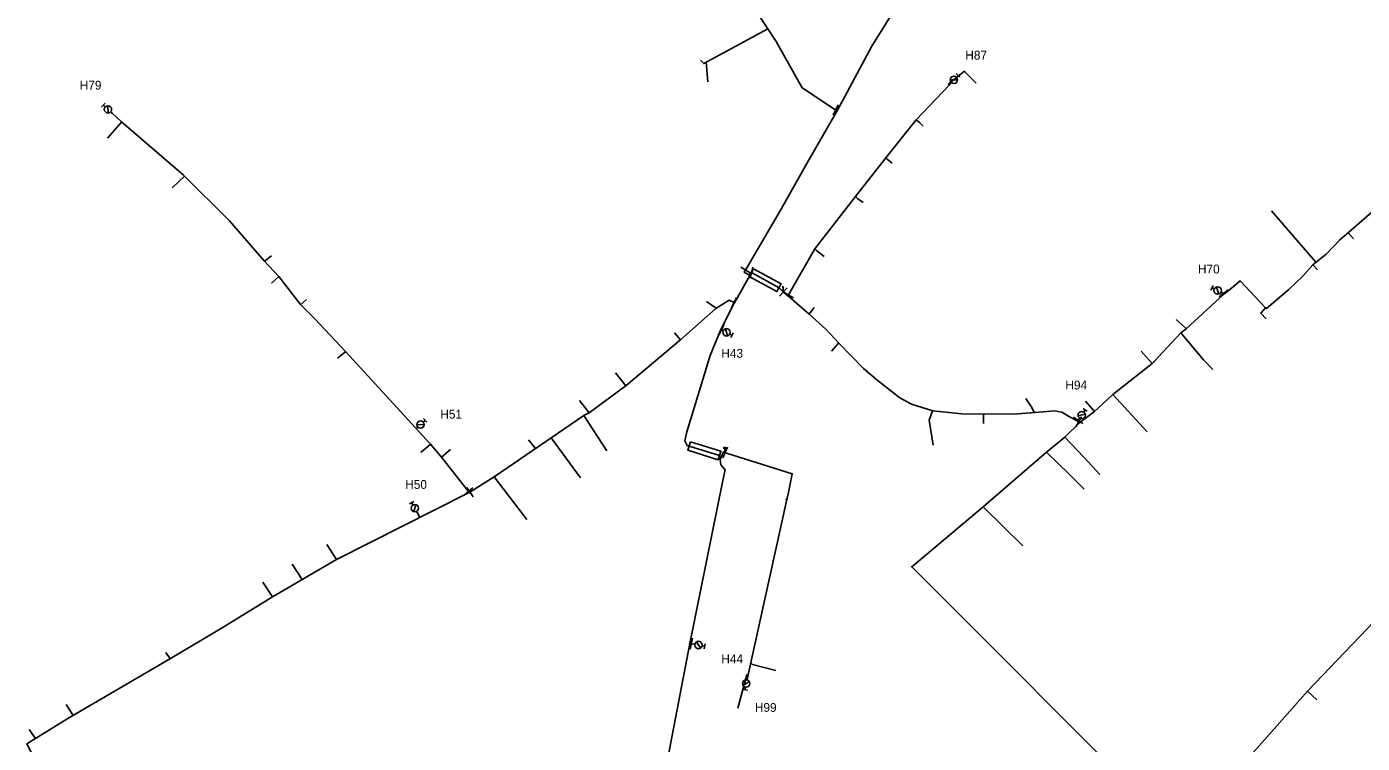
# Model space of a CAD drawing. Extents: x -548873 to -538270, y -1201997 to -1192514.
# Drawn here: x -547608.6 to -547306.8, y -1195915.9 to -1195753.9 of the extents above; entities that cross this region are included whole.
import ezdxf

# ---------------------------------------------------------------- set-up
doc = ezdxf.new("R2010")
doc.units = 0
for name, color, linetype in [('KN_HRAN_STÁTNÍ', 7, 'Continuous'), ('KN_PARC_Č', 7, 'Continuous'), ('KN_VKP_HRAN_SPORNÁ', 7, 'Continuous'), ('PK_PARC_Čv', 7, 'Continuous'), ('Vrstva 29', 7, 'Continuous'), ('Vrstva 37', 7, 'Continuous'), ('Vrstva 39', 7, 'Continuous')]:
    doc.layers.add(name, color=color, linetype=linetype)

# ---------------------------------------------------------------- blocks, each defined once
blk = doc.blocks.new('160')
at = {"layer": 'KN_HRAN_STÁTNÍ'}
blk.add_circle((0, 0), 0.0458, dxfattribs=at)
blk = doc.blocks.new('147')
at = {"layer": 'KN_HRAN_STÁTNÍ'}
blk.add_line((0, 1.27), (0, -1.27), dxfattribs=at)
blk = doc.blocks.new('133')
at = {"layer": 'KN_HRAN_STÁTNÍ'}
for p, q in [((0.28, 0), (0, 0)), ((0.54, 0.58), (1.7, -0.58)), ((1.94, 0), (2.52, 0)), ((2.52, 0.58), (2.52, -0.58))]:
    blk.add_line(p, q, dxfattribs=at)
blk.add_circle((1.11, 0), 0.825, dxfattribs=at)
blk = doc.blocks.new('150')
at = {"layer": 'KN_HRAN_STÁTNÍ'}
blk.add_line((0, 1.27), (0, -1.27), dxfattribs=at)
blk = doc.blocks.new('124')
at = {"layer": 'KN_HRAN_STÁTNÍ'}
for q in [(-0.19, 1.22), (-0.19, 0.92), (0.19, 1.22), (0, 0), (0.19, 0.92)]:
    blk.add_line((0, 1.07), q, dxfattribs=at)
blk = doc.blocks.new('128')
at = {"layer": 'KN_HRAN_STÁTNÍ'}
for p, q in [((-0.19, 1.06), (-0.43, 1.15)), ((-0.36, 0.84), (-0.19, 1.06)), ((-0.19, 1.06), (-0.02, 1.25)), ((-0.19, 1.06), (0, 0)), ((0.05, 0.95), (-0.19, 1.06)), ((-0.1, 1), (0.41, 0.91)), ((-0.07, 0.82), (0.17, 0.96)), ((0.17, 0.96), (-0.02, 1.13)), ((0.17, 0.96), (0, 0)), ((0.19, 1.21), (0.17, 0.96)), ((0.17, 0.96), (0.38, 1.08)), ((0.36, 0.77), (0.17, 0.96))]:
    blk.add_line(p, q, dxfattribs=at)

msp = doc.modelspace()

# ---------------------------------------------------------------- linework, layer by layer
at = {"layer": 'KN_PARC_Č'}
for points in [[(-547441.111, -1195754.422), (-547455.603, -1195762.254), (-547456.318, -1195761.516)], [(-547455.085, -1195761.974), (-547454.684, -1195766.387)], [(-547400.179, -1195767.138), (-547400.328, -1195766.986), (-547399.963, -1195766.62), (-547396.696, -1195763.997), (-547396.579, -1195764.113), (-547396.341, -1195764.352), (-547394.023, -1195766.72)], [(-547407.612, -1195774.975), (-547406.822, -1195775.59), (-547406.001, -1195776.388)], [(-547587.165, -1195775.494), (-547590.347, -1195779.106)], [(-547414.479, -1195783.569), (-547414.147, -1195783.843), (-547413.002, -1195784.775)], [(-547572.927, -1195787.722), (-547575.705, -1195790.36)], [(-547421.344, -1195792.329), (-547420.755, -1195792.797), (-547419.612, -1195793.623)], [(-547317.254, -1195807.158), (-547327.304, -1195795.558)], [(-547309.968, -1195800.545), (-547308.77, -1195801.88)], [(-547430.516, -1195804.133), (-547430.099, -1195804.49), (-547428.425, -1195805.875)], [(-547554.859, -1195806.921), (-547553.305, -1195805.714)], [(-547317.968, -1195807.731), (-547316.922, -1195808.892)], [(-547551.66, -1195810.37), (-547553.281, -1195811.855)], [(-547546.721, -1195816.752), (-547545.362, -1195815.605)], [(-547452.782, -1195817.538), (-547454.961, -1195815.998)], [(-547431.781, -1195818.928), (-547430.687, -1195817.356)], [(-547328.626, -1195817.484), (-547329.726, -1195818.651), (-547328.494, -1195819.929)], [(-547346.549, -1195822.171), (-547348.812, -1195820.119)], [(-547460.852, -1195824.659), (-547462.178, -1195823.122)], [(-547347.764, -1195823.113), (-547342.677, -1195829.179), (-547340.526, -1195831.387)], [(-547425.109, -1195825.409), (-547426.771, -1195827.282)], [(-547536.542, -1195827.389), (-547538.359, -1195828.808)], [(-547354.284, -1195830.016), (-547356.767, -1195827.264)], [(-547473.19, -1195835.059), (-547475.523, -1195832.124)], [(-547481.53, -1195841.2), (-547483.651, -1195838.429)], [(-547380.949, -1195841.122), (-547381.009, -1195840.953), (-547381.473, -1195840.007), (-547382.792, -1195837.99)], [(-547367.307, -1195840.86), (-547369.366, -1195838.544)], [(-547363.145, -1195837.018), (-547355.407, -1195845.49)], [(-547482.687, -1195841.8), (-547477.492, -1195849.807)], [(-547403.881, -1195840.742), (-547404.672, -1195842.813), (-547403.775, -1195848.488)], [(-547392.362, -1195841.445), (-547392.372, -1195843.638)], [(-547493.63, -1195849.273), (-547495.195, -1195847.26)], [(-547490.083, -1195846.85), (-547483.472, -1195855.874)], [(-547373.978, -1195846.717), (-547369.772, -1195851.099), (-547369.542, -1195851.338), (-547366.115, -1195855.158)], [(-547517.358, -1195848.267), (-547519.538, -1195850.131)], [(-547514.874, -1195851.191), (-547512.867, -1195849.443)], [(-547378.124, -1195850.092), (-547373.004, -1195855.024), (-547369.626, -1195858.438)], [(-547502.943, -1195855.635), (-547495.559, -1195865.334)], [(-547436.772, -1195860.566), (-547437.03, -1195860.96)], [(-547392.437, -1195862.445), (-547383.478, -1195871.243)], [(-547538.585, -1195874.329), (-547540.805, -1195870.97)], [(-547439.861, -1195874.545), (-547440.034, -1195874.522)], [(-547546.319, -1195878.829), (-547548.597, -1195875.398)], [(-547553.079, -1195882.763), (-547555.214, -1195879.49)], [(-547576.222, -1195896.778), (-547577.201, -1195895.374)], [(-547444.975, -1195897.681), (-547444.601, -1195898.032), (-547439.279, -1195899.44)], [(-547445.578, -1195900.408), (-547445.773, -1195900.364), (-547445.871, -1195900.43), (-547447.912, -1195907.9)], [(-547319.192, -1195904.074), (-547317.077, -1195906.061)], [(-547598.125, -1195909.581), (-547599.654, -1195907.084)], [(-547606.64, -1195914.798), (-547608.058, -1195912.752)]]:
    msp.add_lwpolyline(points, dxfattribs=at)
at = {"layer": 'KN_VKP_HRAN_SPORNÁ'}
for points in [[(-547425.785, -1195772.759), (-547433.342, -1195767.71), (-547439.235, -1195757.255), (-547443.312, -1195751.099), (-547444.279, -1195749.64), (-547450.389, -1195739.691), (-547459.879, -1195725.68), (-547466.059, -1195717.114), (-547468.493, -1195713.113), (-547468.55, -1195710.024), (-547467.599, -1195689.001), (-547474.02, -1195665.116), (-547488.253, -1195647.01), (-547500.937, -1195632.883), (-547516.701, -1195620.349), (-547516.745, -1195620.314)], [(-547353.907, -1195674.777), (-547358.947, -1195681.231), (-547359.171, -1195687.793), (-547360.282, -1195690.048), (-547367.646, -1195697.265), (-547376.495, -1195705.645), (-547382.898, -1195712.235), (-547393.089, -1195723.345), (-547400.573, -1195732.935), (-547405.899, -1195740.503), (-547411.174, -1195747.949), (-547417.586, -1195758.304), (-547425.386, -1195772.82)], [(-547269.561, -1195765.274), (-547270.596, -1195766.141), (-547287.035, -1195779.881), (-547294.101, -1195786.683), (-547303.328, -1195794.687), (-547309.862, -1195800.458), (-547311.869, -1195802.1)], [(-547436.455, -1195814.564), (-547430.516, -1195804.134), (-547421.344, -1195792.329), (-547414.479, -1195783.569), (-547407.612, -1195774.975), (-547400.103, -1195767.058), (-547399.965, -1195766.913)], [(-547508.788, -1195858.964), (-547514.836, -1195851.236), (-547517.426, -1195848.187), (-547536.588, -1195827.339), (-547543.476, -1195819.949), (-547546.728, -1195816.745), (-547551.623, -1195810.41), (-547554.93, -1195806.844), (-547562.75, -1195797.813), (-547573.276, -1195787.375), (-547587.201, -1195775.463), (-547589.327, -1195773.469), (-547589.353, -1195773.445)], [(-547425.386, -1195772.82), (-547432.316, -1195784.838), (-547438.304, -1195795.553), (-547445.856, -1195808.424), (-547446.172, -1195808.918)], [(-547425.386, -1195772.82), (-547425.785, -1195772.759)], [(-547311.869, -1195802.1), (-547314.943, -1195805.308), (-547317.966, -1195807.729), (-547320.242, -1195810.343), (-547323.407, -1195813.352), (-547328.467, -1195817.647), (-547328.626, -1195817.484), (-547328.629, -1195817.481), (-547334.406, -1195811.367), (-547336.339, -1195812.999), (-547337.597, -1195814.087), (-547338.088, -1195814.408)], [(-547445.172, -1195810.15), (-547448.661, -1195816.302)], [(-547446.172, -1195808.918), (-547446.463, -1195809.412), (-547445.172, -1195810.15)], [(-547445.172, -1195810.15), (-547445.16, -1195809.509), (-547444.847, -1195809.496)], [(-547444.847, -1195809.496), (-547438.592, -1195812.909), (-547437.683, -1195813.835)], [(-547437.611, -1195813.905), (-547437.683, -1195813.835)], [(-547436.579, -1195814.781), (-547437.611, -1195813.905)], [(-547436.579, -1195814.781), (-547436.455, -1195814.564)], [(-547353.892, -1195829.692), (-547347.761, -1195823.111), (-547346.551, -1195822.173), (-547338.088, -1195814.408)], [(-547448.762, -1195816.252), (-547449.848, -1195815.721), (-547452.894, -1195817.607), (-547460.799, -1195824.614), (-547473.138, -1195835.021), (-547481.507, -1195841.188), (-547482.698, -1195841.806), (-547502.943, -1195855.635), (-547508.437, -1195859.105)], [(-547448.661, -1195816.302), (-547448.78, -1195816.543), (-547451.731, -1195822.33), (-547454.152, -1195828.2), (-547459.448, -1195845.518), (-547459.65, -1195846.468), (-547459.862, -1195847.55), (-547459.355, -1195848.577), (-547458.871, -1195848.709), (-547452.034, -1195850.825), (-547451.674, -1195851.182)], [(-547448.661, -1195816.302), (-547448.762, -1195816.252)], [(-547370.858, -1195843.241), (-547373.156, -1195841.974), (-547374.685, -1195841.045), (-547376.328, -1195840.772), (-547378.897, -1195840.944), (-547385.602, -1195841.526), (-547397.292, -1195841.387), (-547403.858, -1195840.749), (-547408.669, -1195839.269), (-547411.319, -1195837.786), (-547416.515, -1195833.753), (-547419.503, -1195831.152), (-547425.059, -1195825.461), (-547428.05, -1195822.298), (-547431.781, -1195818.928), (-547436.393, -1195814.926), (-547436.579, -1195814.781)], [(-547370.601, -1195843.396), (-547367.308, -1195840.86), (-547363.144, -1195837.018), (-547354.287, -1195830.019), (-547353.892, -1195829.692)], [(-547408.612, -1195875.991), (-547392.43, -1195862.44), (-547378.116, -1195850.085), (-547373.973, -1195846.713), (-547370.601, -1195843.396)], [(-547370.601, -1195843.396), (-547370.858, -1195843.241)], [(-547450.749, -1195850.155), (-547451.173, -1195850.009), (-547451.448, -1195850.61), (-547451.674, -1195851.182)], [(-547445.726, -1195901.074), (-547445.499, -1195900.051), (-547436.815, -1195860.769), (-547436.48, -1195859.171), (-547435.598, -1195854.968), (-547450.433, -1195850.288), (-547450.749, -1195850.155)], [(-547451.674, -1195851.182), (-547451.924, -1195851.77), (-547451.742, -1195852.962), (-547450.728, -1195854.049), (-547451.305, -1195856.509), (-547458.717, -1195893.288), (-547462.732, -1195914.137), (-547465.207, -1195927.077)], [(-547508.598, -1195859.206), (-547538.573, -1195874.322), (-547553.093, -1195882.771), (-547564.445, -1195889.747), (-547576.129, -1195896.724), (-547599.306, -1195910.271), (-547608.605, -1195916.011), (-547605.041, -1195922.864)], [(-547508.598, -1195859.206), (-547508.788, -1195858.964)], [(-547508.437, -1195859.105), (-547508.598, -1195859.206)], [(-547424.144, -1196016.765), (-547424.508, -1196016.405), (-547430.282, -1196010.688), (-547417.621, -1195996.885), (-547408.207, -1195986.765), (-547402.107, -1195980.091), (-547388.859, -1195965.775), (-547372.176, -1195948.007), (-547363.002, -1195938.001), (-547356.605, -1195931.025), (-547356.251, -1195929.577), (-547356.667, -1195928.147), (-547358.105, -1195926.546), (-547360.459, -1195924.19), (-547400.597, -1195884.014), (-547408.612, -1195875.991)], [(-547423.899, -1196017.008), (-547412.145, -1196004.69), (-547395.753, -1195987.042), (-547390.663, -1195981.436), (-547374.686, -1195963.838), (-547358.776, -1195946.603), (-547347.545, -1195935.094), (-547330.623, -1195917.023), (-547319.187, -1195904.069), (-547302.312, -1195886.45), (-547300.97, -1195886.17), (-547298.561, -1195886.625), (-547294.438, -1195888.916), (-547286.694, -1195896.655), (-547278.196, -1195905.147)]]:
    msp.add_lwpolyline(points, dxfattribs=at)
at = {"layer": 'PK_PARC_Čv'}
for points in [[(-547399.965, -1195766.913), (-547399.827, -1195766.767)], [(-547589.353, -1195773.445), (-547589.429, -1195773.373)], [(-547338.088, -1195814.408), (-547338.126, -1195814.19), (-547338.432, -1195814.053)], [(-547451.735, -1195822.34), (-547451.461, -1195822.475)], [(-547520.575, -1195844.761), (-547520.411, -1195844.61)], [(-547371.135, -1195843.088), (-547370.814, -1195842.617)], [(-547519.75, -1195864.83), (-547520.374, -1195863.699)], [(-547458.725, -1195893.327), (-547457.902, -1195893.444)], [(-547445.726, -1195901.074), (-547445.769, -1195901.27)]]:
    msp.add_lwpolyline(points, dxfattribs=at)
at = {"layer": 'Vrstva 37'}
for points in [[(-547444.368, -1195808.618), (-547438.113, -1195812.031), (-547439.071, -1195813.787), (-547445.326, -1195810.374), (-547444.368, -1195808.618)], [(-547458.575, -1195847.754), (-547451.738, -1195849.87), (-547452.33, -1195851.78), (-547459.167, -1195849.664), (-547458.575, -1195847.754)]]:
    msp.add_lwpolyline(points, dxfattribs=at)

# ---------------------------------------------------------------- block references
at = {"layer": 'PK_PARC_Čv'}
for name, p, xscale, yscale, rotation in [('133', (-547399.827, -1195766.767), 1.00000000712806, 1.00000000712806, 46.99999943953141), ('133', (-547589.429, -1195773.373), 1.00000000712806, 1.00000000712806, 136.99999943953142), ('133', (-547338.432, -1195814.053), 1.0225848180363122, 1.0225848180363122, 154.18102564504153), ('150', (-547338.126, -1195814.19), 1.000000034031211, 1.0000000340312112, -51.999999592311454), ('150', (-547451.598, -1195822.408), 1.0138865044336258, 1.0138865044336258, -27.56531359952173), ('133', (-547451.461, -1195822.475), 1.0138865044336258, 1.0138865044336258, -27.56531359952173), ('133', (-547370.814, -1195842.617), 0.9999999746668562, 0.999999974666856, 55.999999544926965), ('133', (-547520.411, -1195844.61), 1.00000000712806, 1.00000000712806, 43.0000005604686), ('150', (-547370.987, -1195842.871), 0.9999999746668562, 0.999999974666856, -124.00000045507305), ('133', (-547520.374, -1195863.699), 1.0000000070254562, 1.0000000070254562, 118.99999892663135), ('150', (-547458.428, -1195893.369), 1.0092050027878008, 1.0092050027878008, -11.116918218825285), ('133', (-547457.902, -1195893.444), 1.0092050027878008, 1.0092050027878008, -11.116918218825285), ('133', (-547445.769, -1195901.27), 1.0000000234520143, 1.0000000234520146, -101.99999938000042)]:
    msp.add_blockref(name, p, dxfattribs=dict(at, xscale=xscale, yscale=yscale, rotation=rotation))
at = {"layer": 'Vrstva 29'}
for name, p, xscale, yscale, rotation in [('160', (-547399.965, -1195766.913), 1.00000000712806, 1.00000000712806, 46.99999943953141), ('147', (-547425.785, -1195772.759), 1.0296949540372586, 1.0296949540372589, 155.86620948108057), ('160', (-547589.353, -1195773.445), 1.00000000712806, 1.00000000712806, -43.0000005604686), ('160', (-547425.386, -1195772.82), 1.0106518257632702, 1.0106518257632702, -151.83788426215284), ('160', (-547311.869, -1195802.1), 1.00000000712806, 1.00000000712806, 43.0000005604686), ('147', (-547446.172, -1195808.918), 1.0000000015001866, 1.0000000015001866, -120.99999982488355), ('147', (-547444.847, -1195809.496), 1.0028916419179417, 1.0028916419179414, 166.30279126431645), ('160', (-547445.172, -1195810.15), 0.999999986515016, 0.9999999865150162, -105.00000012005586), ('147', (-547437.611, -1195813.905), 1.0000000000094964, 1.0000000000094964, -42.000001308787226), ('160', (-547437.683, -1195813.835), 1.0000000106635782, 1.0000000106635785, 135.99999834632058), ('147', (-547436.455, -1195814.564), 1.0000000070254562, 1.0000000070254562, 61.000001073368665), ('160', (-547338.088, -1195814.408), 1.000000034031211, 1.0000000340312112, 38.000000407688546), ('147', (-547448.762, -1195816.252), 1.0138865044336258, 1.0138865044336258, 152.43468640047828), ('160', (-547448.661, -1195816.302), 0.9999999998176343, 0.9999999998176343, -116.9999993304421), ('160', (-547436.579, -1195814.781), 1.0000000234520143, 1.0000000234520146, -78.0000006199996), ('160', (-547353.892, -1195829.692), 1.0000000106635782, 1.0000000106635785, 44.00000165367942), ('147', (-547370.858, -1195843.241), 1.0037042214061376, 1.0037042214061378, -29.379208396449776), ('160', (-547370.601, -1195843.396), 1.0000000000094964, 1.0000000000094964, 42.000001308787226), ('147', (-547450.749, -1195850.155), 1.0296949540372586, 1.0296949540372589, -24.133790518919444), ('160', (-547451.674, -1195851.182), 1.0000000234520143, 1.0000000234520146, -78.0000006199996), ('147', (-547508.788, -1195858.964), 1.000000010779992, 1.0000000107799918, 128.99999891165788), ('147', (-547508.437, -1195859.105), 0.9999999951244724, 0.9999999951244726, -146.99999872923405), ('160', (-547508.598, -1195859.206), 1.0000000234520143, 1.0000000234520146, -101.99999938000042), ('160', (-547408.612, -1195875.991), 1.00000001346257, 1.0000000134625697, -91.99999990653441), ('160', (-547445.726, -1195901.074), 1.0000000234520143, 1.0000000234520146, -101.99999938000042)]:
    msp.add_blockref(name, p, dxfattribs=dict(at, xscale=xscale, yscale=yscale, rotation=rotation))
at = {"layer": 'Vrstva 39'}
for name, p in [('124', (-547437.683, -1195813.835)), ('128', (-547450.749, -1195850.155))]:
    msp.add_blockref(name, p, dxfattribs=at)

# ---------------------------------------------------------------- texts
at = {"layer": 'PK_PARC_Čv'}
for s, p in [('H87', (-547396.497, -1195761.367)), ('H79', (-547596.619, -1195768.153)), ('H70', (-547343.922, -1195809.693)), ('H43', (-547451.631, -1195828.745)), ('H94', (-547373.884, -1195835.917)), ('H51', (-547515.131, -1195842.5)), ('H50', (-547523.064, -1195858.379)), ('H44', (-547451.632, -1195897.794)), ('H99', (-547444.049, -1195908.77))]:
    msp.add_text(s, height=2, dxfattribs=at).set_placement(p)

doc.saveas('drawing.dxf')
